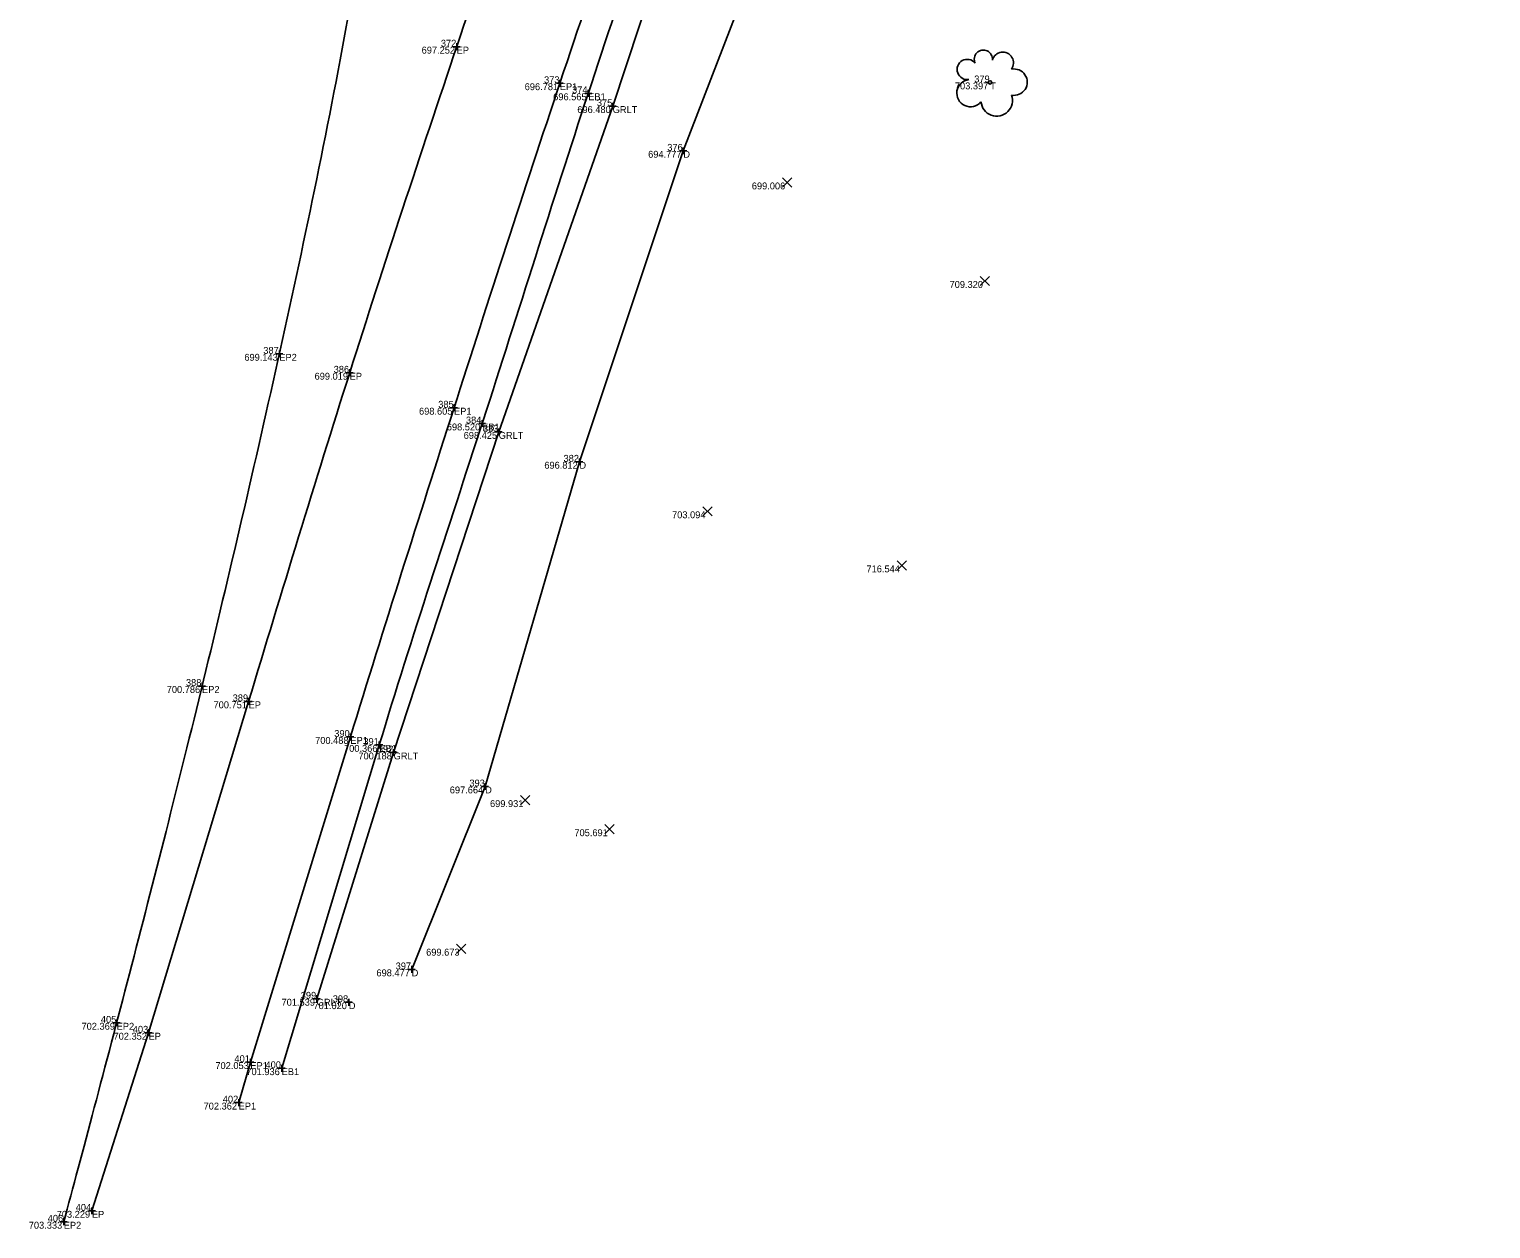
# Model space of a CAD drawing. Extents: x 2197382 to 2204062, y 634117 to 636522.
# Drawn here: x 2201917.4 to 2202128.8, y 634116.8 to 634290.4 of the extents above; entities that cross this region are included whole.
import ezdxf

# ---------------------------------------------------------------- set-up
doc = ezdxf.new("R2010")
doc.units = 0
for name, color, linetype in [('_CIVIL_CONSTRUCTION', 7, 'Continuous'), ('DR_X_Ditch', 7, 'Continuous'), ('GE_P_Alignment_100_Bearings', 7, 'Continuous'), ('GE_P_Alignment_100_Distances', 7, 'Continuous'), ('GE_X_Alignment', 7, 'Continuous'), ('PF_X_Ground_Line', 7, 'Continuous'), ('RW_X_CL_100_Curve_Data', 7, 'Continuous'), ('SH_Border', 7, 'Continuous'), ('SH_Cut_Line', 7, 'Continuous'), ('SH_Data', 7, 'Continuous')]:
    doc.layers.add(name, color=color, linetype=linetype)

msp = doc.modelspace()

# ---------------------------------------------------------------- linework, layer by layer
at = {"layer": '_CIVIL_CONSTRUCTION'}
for p, q in [((2201978.73, 634287.84), (2201979.73, 634287.84)), ((2201979.23, 634288.34), (2201979.23, 634287.34)), ((2201979.23, 634287.84), (2201979.23, 634287.84)), ((2201993.65, 634282.55), (2201994.65, 634282.55)), ((2201994.15, 634283.05), (2201994.15, 634282.05)), ((2201994.15, 634282.55), (2201994.15, 634282.55)), ((2201998.26, 634281.59), (2201998.26, 634280.59)), ((2201997.76, 634281.09), (2201998.76, 634281.09)), ((2201998.26, 634281.09), (2201998.26, 634281.09)), ((2202001.3, 634279.24), (2202002.3, 634279.24)), ((2202001.8, 634279.74), (2202001.8, 634278.74)), ((2202001.8, 634279.24), (2202001.8, 634279.24)), ((2202012.02, 634273.27), (2202012.02, 634272.27)), ((2202011.52, 634272.77), (2202012.52, 634272.77)), ((2202012.02, 634272.77), (2202012.02, 634272.77)), ((2201953.07, 634243.39), (2201954.07, 634243.39)), ((2201953.57, 634243.89), (2201953.57, 634242.89)), ((2201953.57, 634243.39), (2201953.57, 634243.39)), ((2201963.25, 634240.65), (2201964.25, 634240.65)), ((2201963.75, 634241.15), (2201963.75, 634240.15)), ((2201963.75, 634240.65), (2201963.75, 634240.65)), ((2201978.35, 634235.59), (2201979.35, 634235.59)), ((2201978.85, 634236.09), (2201978.85, 634235.09)), ((2201978.85, 634235.59), (2201978.85, 634235.59)), ((2201982.42, 634233.31), (2201983.42, 634233.31)), ((2201982.92, 634233.81), (2201982.92, 634232.81)), ((2201982.92, 634233.31), (2201982.92, 634233.31)), ((2201984.81, 634232.09), (2201985.81, 634232.09)), ((2201985.31, 634232.59), (2201985.31, 634231.59)), ((2201985.31, 634232.09), (2201985.31, 634232.09)), ((2201996.49, 634227.77), (2201997.49, 634227.77)), ((2201996.99, 634228.27), (2201996.99, 634227.27)), ((2201996.99, 634227.77), (2201996.99, 634227.77)), ((2201941.89, 634195.32), (2201942.89, 634195.32)), ((2201942.39, 634195.82), (2201942.39, 634194.82)), ((2201942.39, 634195.32), (2201942.39, 634195.32)), ((2201948.63, 634193.1), (2201949.63, 634193.1)), ((2201949.13, 634193.6), (2201949.13, 634192.6)), ((2201949.13, 634193.1), (2201949.13, 634193.1)), ((2201963.85, 634188.45), (2201963.85, 634187.45)), ((2201963.35, 634187.95), (2201964.35, 634187.95)), ((2201963.85, 634187.95), (2201963.85, 634187.95)), ((2201967.53, 634186.79), (2201968.53, 634186.79)), ((2201968.03, 634187.29), (2201968.03, 634186.29)), ((2201968.03, 634186.79), (2201968.03, 634186.79)), ((2201970.11, 634186.2), (2201970.11, 634185.2)), ((2201969.61, 634185.7), (2201970.61, 634185.7)), ((2201970.11, 634185.7), (2201970.11, 634185.7)), ((2201982.85, 634180.78), (2201983.85, 634180.78)), ((2201983.35, 634181.28), (2201983.35, 634180.28)), ((2201983.35, 634180.78), (2201983.35, 634180.78)), ((2201972.72, 634154.81), (2201972.72, 634153.81)), ((2201972.22, 634154.31), (2201973.22, 634154.31)), ((2201972.72, 634154.31), (2201972.72, 634154.31)), ((2201958.98, 634150.56), (2201958.98, 634149.56)), ((2201958.48, 634150.06), (2201959.48, 634150.06)), ((2201958.98, 634150.06), (2201958.98, 634150.06)), ((2201963.12, 634149.56), (2201964.12, 634149.56)), ((2201963.62, 634150.06), (2201963.62, 634149.06)), ((2201963.62, 634149.56), (2201963.62, 634149.56)), ((2201929.54, 634146.58), (2201930.54, 634146.58)), ((2201930.04, 634147.08), (2201930.04, 634146.08)), ((2201930.04, 634146.58), (2201930.04, 634146.58)), ((2201934.15, 634145.14), (2201935.15, 634145.14)), ((2201934.65, 634145.64), (2201934.65, 634144.64)), ((2201934.65, 634145.14), (2201934.65, 634145.14)), ((2201948.88, 634140.89), (2201949.88, 634140.89)), ((2201949.38, 634141.39), (2201949.38, 634140.39)), ((2201949.38, 634140.89), (2201949.38, 634140.89)), ((2201953.41, 634140.01), (2201954.41, 634140.01)), ((2201953.91, 634140.51), (2201953.91, 634139.51)), ((2201953.91, 634140.01), (2201953.91, 634140.01)), ((2201947.69, 634135.53), (2201947.69, 634134.53)), ((2201947.19, 634135.03), (2201948.19, 634135.03)), ((2201947.69, 634135.03), (2201947.69, 634135.03)), ((2201925.95, 634119.37), (2201926.95, 634119.37)), ((2201926.45, 634119.87), (2201926.45, 634118.87)), ((2201926.45, 634119.37), (2201926.45, 634119.37)), ((2201921.88, 634117.79), (2201922.88, 634117.79)), ((2201922.38, 634118.29), (2201922.38, 634117.29)), ((2201922.38, 634117.79), (2201922.38, 634117.79))]:
    msp.add_line(p, q, dxfattribs=at)
at = {"layer": 'DR_X_Ditch'}
msp.add_lwpolyline([(2202157.96, 634604.45), (2202148.75, 634589.47), (2202127.84, 634547.21), (2202104.93, 634504.72), (2202083.04, 634458.9), (2202069.26, 634411.57), (2202046.4, 634367.52), (2202030.7, 634321.28), (2202012.02, 634272.77), (2201996.99, 634227.77), (2201983.35, 634180.78), (2201972.72, 634154.31)], dxfattribs=at)
at = {"layer": 'GE_P_Alignment_100_Bearings'}
msp.add_circle((2202056.41, 634282.67), 0.24, dxfattribs=at)
for centre, radius, start, end in [((2202053.1, 634284.54), 1.47, 39.0625, 279.5412), ((2202055.43, 634286.04), 1.32, 354.0047, 205.9741), ((2202058.24, 634285.5), 1.55, 323.83, 165.0376), ((2202059.87, 634282.71), 1.91, 259.1453, 101.4596), ((2202053.56, 634281.12), 1.97, 96.1722, 320.5737), ((2202057.36, 634280.07), 2.28, 184.9476, 19.4572)]:
    msp.add_arc(centre, radius, start, end, dxfattribs=at)
at = {"layer": 'GE_P_Alignment_100_Distances'}
for p, q in [((2201949.13, 634193.1), (2201934.65, 634145.14)), ((2201963.85, 634187.95), (2201949.38, 634140.89)), ((2201934.65, 634145.14), (2201926.45, 634119.37)), ((2201949.38, 634140.89), (2201947.69, 634135.03))]:
    msp.add_line(p, q, dxfattribs=at)
for points in [[(2202514.19, 635120), (2202501.95, 635108.79), (2202477.63, 635085.87), (2202443.41, 635049.36), (2202409.55, 635012.34), (2202376.26, 634974.99), (2202344.34, 634936.42), (2202312.72, 634897.79), (2202282.43, 634858.12), (2202252.58, 634818.18), (2202223.74, 634777.45), (2202196.69, 634735.5), (2202169.8, 634693.41), (2202144.64, 634650.36), (2202119.18, 634607.44), (2202097.03, 634562.79), (2202074.71, 634518.18), (2202053.15, 634473.28), (2202032.85, 634427.72), (2202013.67, 634381.72), (2201995.41, 634335.21), (2201979.19, 634288.02), (2201963.55, 634240.68), (2201953.92, 634208.98), (2201949.13, 634193.1)], [(2202525.02, 635108.11), (2202513.04, 635097.11), (2202489.33, 635074.07), (2202455.07, 635038.62), (2202421.29, 635002.1), (2202388.81, 634964.35), (2202356.35, 634926.75), (2202325.87, 634887.43), (2202295, 634848.95), (2202265.53, 634808.92), (2202237.35, 634768.89), (2202211.52, 634726.54), (2202183.6, 634685.47), (2202158.14, 634642.34), (2202133.69, 634599.43), (2202111.05, 634555.42), (2202088.76, 634511.33), (2202068.04, 634466.33), (2202047.21, 634421.56), (2202027.88, 634376.06), (2202010.16, 634329.7), (2201994.09, 634282.81), (2201978.74, 634235.43), (2201968.75, 634203.87), (2201963.85, 634187.95)], [(2201977.17, 634458.41), (2201974.18, 634438.92), (2201978.36, 634400.6), (2201972.08, 634345.48), (2201964.26, 634293.48), (2201953.85, 634243.8), (2201942.48, 634194.98), (2201931.83, 634153.17), (2201924.97, 634127.38), (2201922.38, 634117.79)]]:
    msp.add_open_spline(points, degree=3, dxfattribs=at)
at = {"layer": 'GE_X_Alignment'}
msp.add_line((2201968.03, 634186.79), (2201953.91, 634140.01), dxfattribs=at)
msp.add_open_spline([(2202570.92, 635145.14), (2202556.1, 635132.41), (2202530.6, 635107.02), (2202492.19, 635071.28), (2202457.98, 635035.82), (2202424.73, 634999.38), (2202391.64, 634962.22), (2202359.56, 634924.46), (2202328.32, 634885.6), (2202298.37, 634846.53), (2202268.85, 634806.21), (2202240.94, 634765.59), (2202212.91, 634724.71), (2202187.2, 634682.69), (2202161.14, 634640.35), (2202137.99, 634596.95), (2202114.64, 634553.56), (2202092.28, 634509.95), (2202071.73, 634464.7), (2202050.81, 634420.11), (2202031.84, 634374.34), (2202014.23, 634328.21), (2201997.98, 634281.03), (2201983.22, 634233.69), (2201972.74, 634202.38), (2201968.03, 634186.79)], degree=3, dxfattribs=at)
at = {"layer": 'PF_X_Ground_Line'}
msp.add_lwpolyline([(2202017.93, 634327.94), (2202017.35, 634326.25), (2202001.8, 634279.24), (2201985.31, 634232.09), (2201970.11, 634185.7), (2201958.98, 634150.06)], dxfattribs=at)
at = {"layer": 'RW_X_CL_100_Curve_Data'}
for p, q in [((2202026.37, 634267.52), (2202027.7, 634268.85)), ((2202026.37, 634268.85), (2202027.7, 634267.52)), ((2202054.98, 634253.26), (2202056.32, 634254.6)), ((2202054.98, 634254.6), (2202056.32, 634253.26)), ((2202014.84, 634219.93), (2202016.18, 634221.27)), ((2202014.84, 634221.27), (2202016.18, 634219.93)), ((2202042.97, 634212.1), (2202044.3, 634213.44)), ((2202042.97, 634213.44), (2202044.3, 634212.1)), ((2201988.46, 634178.13), (2201989.8, 634179.47)), ((2201988.46, 634179.47), (2201989.8, 634178.13)), ((2202000.68, 634173.92), (2202002.01, 634175.26)), ((2202000.68, 634175.26), (2202002.01, 634173.92)), ((2201979.21, 634156.63), (2201980.54, 634157.96)), ((2201979.21, 634157.96), (2201980.54, 634156.63))]:
    msp.add_line(p, q, dxfattribs=at)

# ---------------------------------------------------------------- texts
at = {"layer": 'SH_Border'}
for s, p in [('EP', (2201979.23, 634286.84)), ('EP1', (2201994.15, 634281.55)), ('T', (2202056.41, 634281.67)), ('EB1', (2201998.26, 634280.09)), ('GRLT', (2202001.8, 634278.24)), ('D', (2202012.02, 634271.77)), ('EP2', (2201953.57, 634242.39)), ('EP', (2201963.75, 634239.65)), ('EP1', (2201978.85, 634234.59)), ('EB1', (2201982.92, 634232.31)), ('GRLT', (2201985.31, 634231.09)), ('D', (2201996.99, 634226.77)), ('EP2', (2201942.39, 634194.32)), ('EP', (2201949.13, 634192.1)), ('EP1', (2201963.85, 634186.95)), ('EB1', (2201968.03, 634185.79)), ('GRLT', (2201970.11, 634184.7)), ('D', (2201983.35, 634179.78)), ('D', (2201972.72, 634153.31)), ('GRLT', (2201958.98, 634149.06)), ('D', (2201963.62, 634148.56)), ('EP2', (2201930.04, 634145.58)), ('EP', (2201934.65, 634144.14)), ('EP1', (2201949.38, 634139.89)), ('EB1', (2201953.91, 634139.01)), ('EP1', (2201947.69, 634134.03)), ('EP', (2201926.45, 634118.37)), ('EP2', (2201922.38, 634116.79))]:
    msp.add_text(s, height=1, dxfattribs=at).set_placement(p)
at = {"layer": 'SH_Cut_Line'}
for s, p in [('372', (2201976.94, 634287.84)), ('373', (2201991.87, 634282.55)), ('379', (2202054.11, 634282.67)), ('374', (2201995.92, 634281.09)), ('375', (2201999.51, 634279.24)), ('376', (2202009.7, 634272.77)), ('387', (2201951.25, 634243.39)), ('386', (2201961.43, 634240.65)), ('385', (2201976.56, 634235.59)), ('384', (2201980.57, 634233.31)), ('383', (2201983.03, 634232.09)), ('382', (2201994.69, 634227.77)), ('388', (2201940.06, 634195.32)), ('389', (2201946.82, 634193.1)), ('390', (2201961.52, 634187.95)), ('391', (2201965.73, 634186.79)), ('392', (2201967.82, 634185.7)), ('393', (2201981.07, 634180.78)), ('397', (2201970.4, 634154.31)), ('399', (2201956.67, 634150.06)), ('398', (2201961.3, 634149.56)), ('405', (2201927.75, 634146.58)), ('403', (2201932.37, 634145.14)), ('401', (2201947.08, 634140.89)), ('400', (2201951.57, 634140.01)), ('402', (2201945.39, 634135.03)), ('406', (2201920.06, 634117.79)), ('404', (2201924.11, 634119.37))]:
    msp.add_text(s, height=1, dxfattribs=at).set_placement(p)
at = {"layer": 'SH_Data'}
for s, p in [('697.252', (2201974.16, 634286.84)), ('696.781', (2201989.07, 634281.55)), ('703.397', (2202051.31, 634281.67)), ('696.565', (2201993.19, 634280.09)), ('696.480', (2201996.68, 634278.24)), ('694.777', (2202006.93, 634271.77)), ('699.006', (2202021.93, 634267.19)), ('709.320', (2202050.54, 634252.93)), ('699.143', (2201948.51, 634242.39)), ('699.019', (2201958.67, 634239.65)), ('698.605', (2201973.78, 634234.59)), ('698.520', (2201977.8, 634232.31)), ('698.425', (2201980.24, 634231.09)), ('696.812', (2201991.91, 634226.77)), ('703.094', (2202010.39, 634219.6)), ('716.544', (2202038.52, 634211.77)), ('700.786', (2201937.28, 634194.32)), ('700.751', (2201944.05, 634192.1)), ('700.488', (2201958.75, 634186.95)), ('700.366', (2201962.93, 634185.79)), ('700.188', (2201965.01, 634184.7)), ('697.664', (2201978.23, 634179.78)), ('699.931', (2201984.05, 634177.8)), ('705.691', (2201996.26, 634173.59)), ('699.673', (2201974.81, 634156.3)), ('698.477', (2201967.62, 634153.31)), ('701.539', (2201953.89, 634149.06)), ('701.020', (2201958.51, 634148.56)), ('702.369', (2201924.95, 634145.58)), ('702.352', (2201929.58, 634144.14)), ('702.053', (2201944.32, 634139.89)), ('701.936', (2201948.8, 634139.01)), ('702.362', (2201942.61, 634134.03)), ('703.229', (2201921.36, 634118.37)), ('703.333', (2201917.32, 634116.79))]:
    msp.add_text(s, height=1, dxfattribs=at).set_placement(p)

doc.saveas('drawing.dxf')
